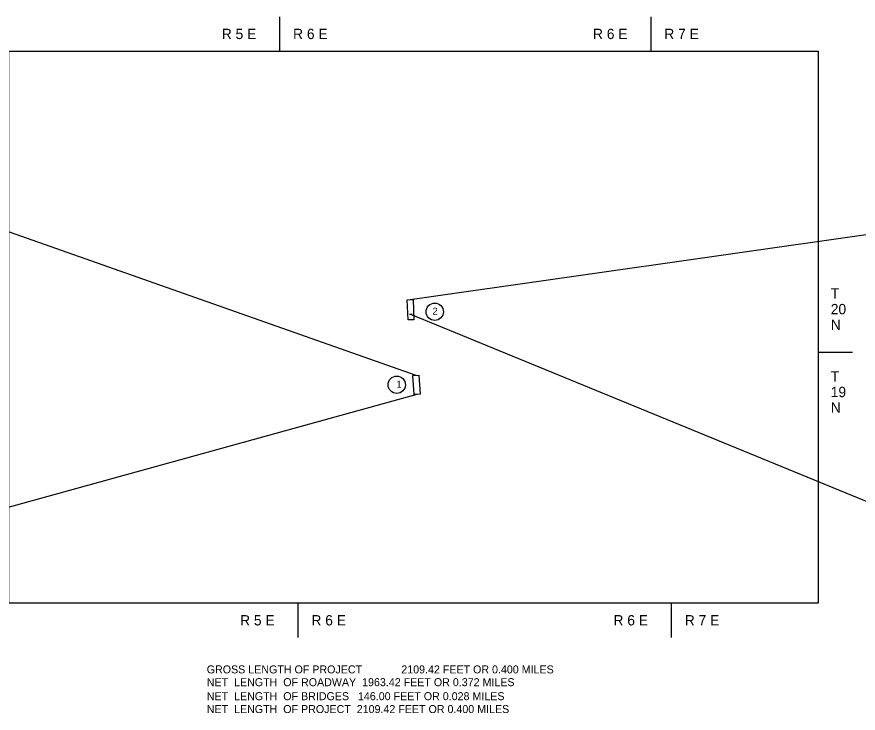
# Model space of a CAD drawing. Extents: x 1334737.7 to 1334827.2, y 402732.3 to 402753.5.
# Drawn here: x 1334746.63 to 1334760.94, y 402732.33 to 402744.16 of the extents above; entities that cross this region are included whole.
import ezdxf

# ---------------------------------------------------------------- set-up
doc = ezdxf.new("R2010")
doc.units = 0
for name, color, linetype in [('Default', 7, 'Continuous'), ('R_No Plot', 7, 'Continuous'), ('R_Temp Easement Annot', 7, 'Continuous')]:
    doc.layers.add(name, color=color, linetype=linetype)

msp = doc.modelspace()

# ---------------------------------------------------------------- linework, layer by layer
at = {"layer": 'Default'}
for p, q in [((1334751.1, 402743.575), (1334751.1, 402744.16)), ((1334757.413, 402743.575), (1334757.413, 402744.16)), ((1334745.66, 402740.796), (1334753.411, 402738.069)), ((1334762.153, 402740.608), (1334753.316, 402739.352)), ((1334753.352, 402739.104), (1334753.302, 402739.103)), ((1334762.153, 402735.482), (1334753.327, 402739.104)), ((1334760.256, 402738.459), (1334760.84, 402738.459)), ((1334745.66, 402735.602), (1334753.434, 402737.746)), ((1334751.412, 402733.611), (1334751.412, 402734.195)), ((1334757.762, 402733.611), (1334757.762, 402734.195))]:
    msp.add_line(p, q, dxfattribs=at)
for points in [[(1334753.266, 402739.35), (1334753.366, 402739.354), (1334753.379, 402739.013), (1334753.279, 402739.012)], [(1334753.384, 402737.742), (1334753.361, 402738.066), (1334753.461, 402738.072), (1334753.484, 402737.749)]]:
    msp.add_lwpolyline(points, close=True, dxfattribs=at)
at = {"layer": 'R_No Plot'}
for centre in [(1334753.734, 402739.148), (1334753.088, 402737.907)]:
    msp.add_circle(centre, 0.147, dxfattribs=at)
at = {"layer": 'R_Temp Easement Annot'}
msp.add_lwpolyline([(1334746.491, 402743.575), (1334760.256, 402743.575), (1334760.256, 402734.195), (1334746.491, 402734.195)], close=True, dxfattribs=at)

# ---------------------------------------------------------------- texts
at = {"layer": 'Default'}
for s, height, p in [('R 5 E', 0.1758, (1334750.111, 402743.782)), ('R 6 E', 0.1758, (1334751.324, 402743.782)), ('R 6 E', 0.1758, (1334756.425, 402743.782)), ('R 7 E', 0.1758, (1334757.638, 402743.782)), ('T', 0.176, (1334760.469, 402739.37)), ('20', 0.1758, (1334760.469, 402739.105)), ('N', 0.176, (1334760.469, 402738.84)), ('T', 0.176, (1334760.469, 402737.962)), ('19', 0.1758, (1334760.469, 402737.697)), ('N', 0.176, (1334760.469, 402737.433)), ('R 5 E', 0.1758, (1334750.423, 402733.817)), ('R 6 E', 0.1758, (1334751.636, 402733.817)), ('R 6 E', 0.1758, (1334756.773, 402733.817)), ('R 7 E', 0.1758, (1334757.986, 402733.817)), ('GROSS LENGTH OF PROJECT', 0.13573, (1334749.856, 402733.002)), (' 2109.42 FEET OR 0.400 MILES', 0.13573, (1334753.114, 402733.002)), ('NET  LENGTH  OF ROADWAY  1963.42 FEET OR 0.372 MILES', 0.13573, (1334749.856, 402732.785)), ('NET  LENGTH  OF BRIDGES   146.00 FEET OR 0.028 MILES', 0.13573, (1334749.856, 402732.547)), ('NET  LENGTH  OF PROJECT  2109.42 FEET OR 0.400 MILES', 0.13573, (1334749.856, 402732.328))]:
    msp.add_text(s, height=height, dxfattribs=at).set_placement(p)
at = {"layer": 'R_No Plot'}
for s, p in [('2', (1334753.696, 402739.1)), ('1', (1334753.083, 402737.859))]:
    msp.add_text(s, height=0.117, rotation=360, dxfattribs=at).set_placement(p)

doc.saveas('drawing.dxf')
